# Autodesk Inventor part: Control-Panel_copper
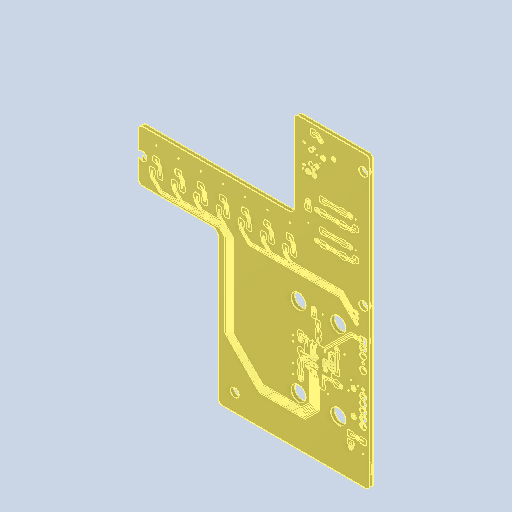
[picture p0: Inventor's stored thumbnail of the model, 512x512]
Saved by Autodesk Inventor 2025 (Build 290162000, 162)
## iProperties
Created: 2026-09
Part Number: Control-Panel_copper
Material: Generic
Document SubType Name: Modeling
Designer: Leonardo
Density: 1 g/cm^3
Appearance: Default
Author: Leonardo
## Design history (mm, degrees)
feature "Base1"
feature "Base2"
feature "Base3"
feature "Base4"
feature "Base5"
feature "Base6"
feature "Base7"
feature "Base8"
feature "Base9"
feature "Base10"
feature "Base11"
feature "Base12"
feature "Base13"
feature "Base14"
feature "Base15"
feature "Base16"
feature "Base17"
feature "Base18"
feature "Base19"
feature "Base20"
feature "Base21"
feature "Base22"
feature "Base23"
feature "Base24"
feature "Base25"
feature "Base26"
feature "Base27"
feature "Base28"
feature "Base29"
feature "Base30"
feature "Base31"
feature "Base32"
feature "Base33"
feature "Base34"
feature "Base35"
feature "Base36"
feature "Base37"
feature "Base38"
feature "Base39"
feature "Base40"
feature "Base41"
feature "Base42"
feature "Base43"
feature "Base44"
feature "Base45"
feature "Base46"
feature "Base47"
feature "Base48"
feature "Base49"
feature "Base50"
feature "Base51"
feature "Base52"
feature "Base53"
feature "Base54"
feature "Base55"
feature "Base56"
feature "Base57"
feature "Base58"
feature "Base59"
feature "Base60"
feature "Base61"
feature "Base62"
feature "Base63"
feature "Base64"
feature "Base65"
feature "Base66"
feature "Base67"
feature "Base68"
feature "Base69"
feature "Base70"
feature "Base71"
feature "Base72"
feature "Base73"
feature "Base74"
feature "Base75"
feature "Base76"
feature "Base77"
feature "Base78"
feature "Base79"
feature "Base80"
feature "Base81"
feature "Base82"
feature "Base83"
feature "Base84"
feature "Base85"
feature "Base86"
feature "Base87"
feature "Base88"
feature "Base89"
feature "Base90"
feature "Base91"
feature "Base92"
feature "Base93"
feature "Base94"
feature "Base95"
feature "Base96"
feature "Base97"
feature "Base98"
feature "Base99"
feature "Base100"
feature "Base101"
feature "Base102"
feature "Base103"
feature "Base104"
feature "Base105"
feature "Base106"
feature "Base107"
feature "Base108"
feature "Base109"
feature "Base110"
feature "Base111"
feature "Base112"
feature "Base113"
feature "Base114"
feature "Base115"
feature "Base116"
feature "Base117"
feature "Base118"
feature "Base119"
feature "Base120"
feature "Base121"
feature "Base122"
feature "Base123"
feature "Base124"
feature "Base125"
feature "Base126"
feature "Base127"
feature "Base128"
feature "Base129"
feature "Base130"
feature "Base131"
feature "Base132"
feature "Base133"
feature "Base134"
feature "Base135"
feature "Base136"
feature "Base137"
feature "Base138"
feature "Base139"
feature "Base140"
feature "Base141"
feature "Base142"
feature "Base143"
feature "Base144"
feature "Base145"
feature "Base146"
feature "Base147"
feature "Base148"
feature "Base149"
feature "Base150"
feature "Base151"
feature "Base152"
feature "Base153"
feature "Base154"
body "Solid1"
body "Solid2"
body "Solid3"
body "Solid4"
body "Solid5"
body "Solid6"
body "Solid7"
body "Solid8"
body "Solid9"
body "Solid10"
body "Solid11"
body "Solid12"
body "Solid13"
body "Solid14"
body "Solid15"
body "Solid16"
body "Solid17"
body "Solid18"
body "Solid19"
body "Solid20"
body "Solid21"
body "Solid22"
body "Solid23"
body "Solid24"
body "Solid25"
body "Solid26"
body "Solid27"
body "Solid28"
body "Solid29"
body "Solid30"
body "Solid31"
body "Solid32"
body "Solid33"
body "Solid34"
body "Solid35"
body "Solid36"
body "Solid37"
body "Solid38"
body "Solid39"
body "Solid40"
body "Solid41"
body "Solid42"
body "Solid43"
body "Solid44"
body "Solid45"
body "Solid46"
body "Solid47"
body "Solid48"
body "Solid49"
body "Solid50"
body "Solid51"
body "Solid52"
body "Solid53"
body "Solid54"
body "Solid55"
body "Solid56"
body "Solid57"
body "Solid58"
body "Solid59"
body "Solid60"
body "Solid61"
body "Solid62"
body "Solid63"
body "Solid64"
body "Solid65"
body "Solid66"
body "Solid67"
body "Solid68"
body "Solid69"
body "Solid70"
body "Solid71"
body "Solid72"
body "Solid73"
body "Solid74"
body "Solid75"
body "Solid76"
body "Solid77"
body "Solid78"
body "Solid79"
body "Solid80"
body "Solid81"
body "Solid82"
body "Solid83"
body "Solid84"
body "Solid85"
body "Solid86"
body "Solid87"
body "Solid88"
body "Solid89"
body "Solid90"
body "Solid91"
body "Solid92"
body "Solid93"
body "Solid94"
body "Solid95"
body "Solid96"
body "Solid97"
body "Solid98"
body "Solid99"
body "Solid100"
body "Solid101"
body "Solid102"
body "Solid103"
body "Solid104"
body "Solid105"
body "Solid106"
body "Solid107"
body "Solid108"
body "Solid109"
body "Solid110"
body "Solid111"
body "Solid112"
body "Solid113"
body "Solid114"
body "Solid115"
body "Solid116"
body "Solid117"
body "Solid118"
body "Solid119"
body "Solid120"
body "Solid121"
body "Solid122"
body "Solid123"
body "Solid124"
body "Solid125"
body "Solid126"
body "Solid127"
body "Solid128"
body "Solid129"
body "Solid130"
body "Solid131"
body "Solid132"
body "Solid133"
body "Solid134"
body "Solid135"
body "Solid136"
body "Solid137"
body "Solid138"
body "Solid139"
body "Solid140"
body "Solid141"
body "Solid142"
body "Solid143"
body "Solid144"
body "Solid145"
body "Solid146"
body "Solid147"
body "Solid148"
body "Solid149"
body "Solid150"
body "Solid151"
body "Solid152"
body "Solid153"
body "Solid154"
